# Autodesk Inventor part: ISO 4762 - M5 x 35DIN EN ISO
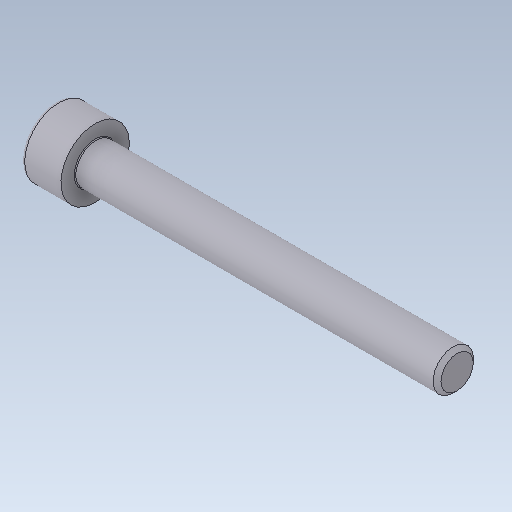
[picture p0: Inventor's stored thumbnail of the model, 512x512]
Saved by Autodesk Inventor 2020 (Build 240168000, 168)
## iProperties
Created: 2017-11
Part Number: ISO 4762 - M5 x 35DIN EN ISO
Material: Ogólny
Document SubType Name: Modeling
Designer: Tomasz
Density: 1 g/cm^3
Appearance: Domyślna
Author: Tomasz
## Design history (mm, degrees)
feature "Solid1"
node "Bryła1"
